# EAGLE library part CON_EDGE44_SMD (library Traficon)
SMD pads for cardedge on US-boards 22+22 pins .156" pitch
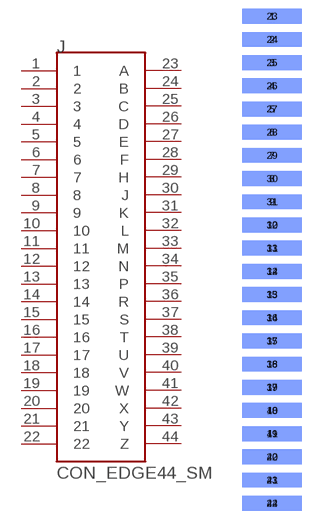
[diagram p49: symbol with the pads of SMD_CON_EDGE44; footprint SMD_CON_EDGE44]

Designator prefix J

## CON_EDGE44_SMD  [SMD_CON_EDGE44]
1  1
2  2
3  3
4  4
5  5
6  6
7  7
8  8
9  9
10  10
11  11
12  12
13  13
14  14
15  15
16  16
17  17
18  18
19  19
20  20
21  21
22  22
23  A
24  B
25  C
26  D
27  E
28  F
29  H
30  J
31  K
32  L
33  M
34  N
35  P
36  R
37  S
38  T
39  U
40  V
41  W
42  X
43  Y
44  Z

## Footprint SMD_CON_EDGE44 (pad centres in mm)
smd 10.16 x 2.54: 1 0,35.662; 2 0,31.699; 3 0,27.737; 4 0,23.774; 5 0,19.812; 6 0,15.85; 7 0,11.887; 8 0,7.925; 9 0,3.962; 10 0,0; 11 0,-3.962; 12 0,-7.925; 13 0,-11.887; 14 0,-15.85; 15 0,-19.812; 16 0,-23.774; 17 0,-27.737; 18 0,-31.699; 19 0,-35.662; 20 0,-39.624; 21 0,-43.586; 22 0,-47.549
smd 10.16 x 2.54 bottom: 23 0,35.662; 24 0,31.699; 25 0,27.737; 26 0,23.774; 27 0,19.812; 28 0,15.85; 29 0,11.887; 30 0,7.925; 31 0,3.962; 32 0,0; 33 0,-3.962; 34 0,-7.925; 35 0,-11.887; 36 0,-15.85; 37 0,-19.812; 38 0,-23.774; 39 0,-27.737; 40 0,-31.699; 41 0,-35.662; 42 0,-39.624; 43 0,-43.586; 44 0,-47.549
